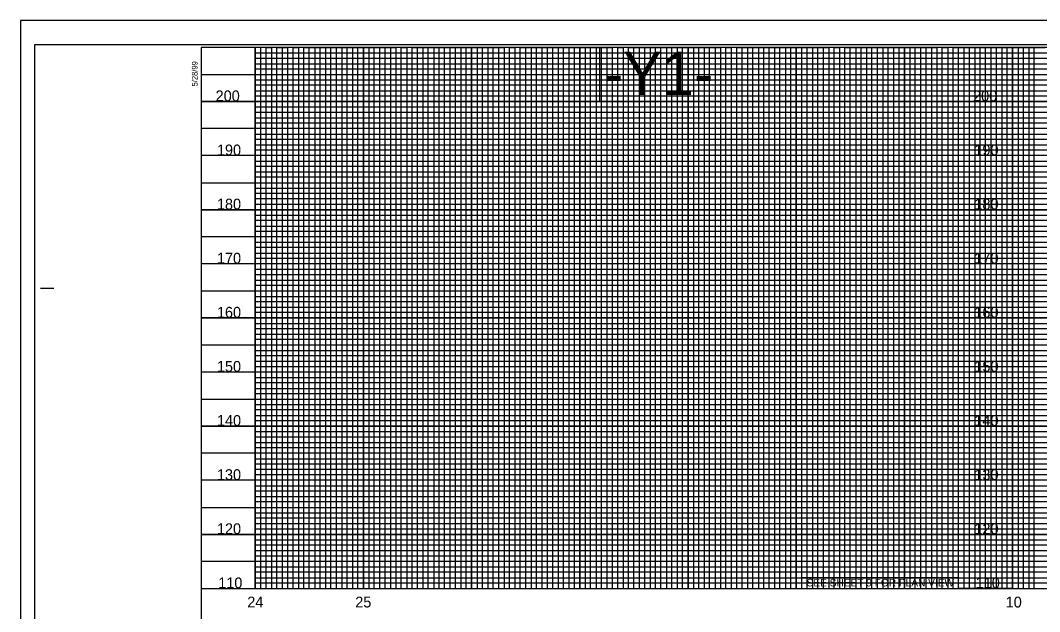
# Model space of a CAD drawing. Extents: x 1779926 to 1781626, y 618464 to 619564.
# Drawn here: x 1779926 to 1780868, y 619018 to 619564 of the extents above; entities that cross this region are included whole.
import ezdxf

# ---------------------------------------------------------------- set-up
doc = ezdxf.new("R2010")
doc.units = 0
for name, color, linetype in [('Exist Vertical Profile Horizontal Axis Label Major', 7, 'Continuous'), ('Exist Vertical Profile Vertical Axis Label', 7, 'Continuous'), ('Prop DSN Text', 7, 'Continuous'), ('Prop Grid Mask', 7, 'Continuous'), ('Sheet DOT Grid CELL', 7, 'Continuous'), ('Sheet Layout Profile Border Port 1', 7, 'Continuous'), ('Sheet Plot Border Inside CELL', 7, 'Continuous'), ('Sheet Plot Border Outside CELL', 7, 'Continuous'), ('Sheet Profile CELL', 7, 'Continuous'), ('Sheet Profile Grid Major CELL', 7, 'Continuous'), ('Sheet Profile Grid Middle CELL', 7, 'Continuous'), ('Sheet Profile Grid Minor CELL', 7, 'Continuous')]:
    doc.layers.add(name, color=color, linetype=linetype)

msp = doc.modelspace()

# ---------------------------------------------------------------- linework, layer by layer
at = {"layer": 'Prop Grid Mask'}
for points in [[(1780577.96, 619539.19), (1780461.31, 619539.19), (1780461.31, 619489.19), (1780577.96, 619489.19)], [(1780792.96, 619539.19), (1780842.96, 619539.19), (1780842.96, 619039.19), (1780792.96, 619039.19)], [(1780792.96, 619049.19), (1780647.96, 619049.19), (1780647.96, 619039.19), (1780792.96, 619039.19)]]:
    msp.add_lwpolyline(points, close=True, dxfattribs=at)
at = {"layer": 'Sheet DOT Grid CELL'}
for p, q in [((1780142.96, 619039.19), (1780142.96, 619539.19)), ((1780192.96, 619039.19), (1780192.96, 619539.19)), ((1780242.96, 619039.19), (1780242.96, 619539.19)), ((1780292.96, 619039.19), (1780292.96, 619539.19)), ((1780342.96, 619039.19), (1780342.96, 619539.19)), ((1780392.96, 619039.19), (1780392.96, 619539.19)), ((1780392.96, 619039.19), (1780392.96, 619539.19)), ((1780442.96, 619039.19), (1780442.96, 619539.19)), ((1780492.96, 619039.19), (1780492.96, 619539.19)), ((1780542.96, 619039.19), (1780542.96, 619539.19)), ((1780592.96, 619039.19), (1780592.96, 619539.19)), ((1780642.96, 619039.19), (1780642.96, 619539.19)), ((1780692.96, 619039.19), (1780692.96, 619539.19)), ((1780742.96, 619039.19), (1780742.96, 619539.19)), ((1780792.96, 619039.19), (1780792.96, 619539.19)), ((1780842.96, 619039.19), (1780842.96, 619539.19)), ((1781392.91, 619489.19), (1780092.96, 619489.19)), ((1781392.91, 619439.19), (1780092.96, 619439.19)), ((1781392.96, 619389.19), (1780092.96, 619389.19)), ((1781392.91, 619339.19), (1780092.96, 619339.19)), ((1781592.96, 619289.19), (1780092.96, 619289.19)), ((1781592.96, 619239.19), (1780092.96, 619239.19)), ((1781592.96, 619189.19), (1780092.96, 619189.19)), ((1781592.96, 619139.19), (1780092.96, 619139.19)), ((1781592.96, 619089.19), (1780092.96, 619089.19))]:
    msp.add_line(p, q, dxfattribs=at)
at = {"layer": 'Sheet Layout Profile Border Port 1'}
for points in [[(1781542.96, 619099.19), (1781542.96, 619314.19), (1781392.91, 619314.19), (1781392.96, 619539.19), (1780142.96, 619539.19), (1780142.96, 619039.19), (1781542.96, 619039.19), (1781542.96, 619049.19)], [(1780142.96, 619378.14), (1780142.96, 619039.19), (1781542.96, 619039.19), (1781542.96, 619314.19)]]:
    msp.add_lwpolyline(points, dxfattribs=at)
at = {"layer": 'Sheet Plot Border Inside CELL'}
msp.add_lwpolyline([(1779938.96, 618486.64), (1781605.46, 618486.64), (1781605.46, 619541.74), (1779938.96, 619541.74)], close=True, dxfattribs=at)
at = {"layer": 'Sheet Plot Border Outside CELL'}
msp.add_lwpolyline([(1779925.96, 618464.19), (1781625.96, 618464.19), (1781625.96, 619564.19), (1779925.96, 619564.19)], close=True, dxfattribs=at)
at = {"layer": 'Sheet Profile CELL'}
for p, q in [((1779944.46, 619316.69), (1779956.96, 619316.69)), ((1780092.96, 619039.19), (1781592.96, 619039.19))]:
    msp.add_line(p, q, dxfattribs=at)
msp.add_lwpolyline([(1781592.96, 619539.19), (1780092.96, 619539.19), (1780092.96, 618489.19), (1781592.96, 618489.19)], close=True, dxfattribs=at)
at = {"layer": 'Sheet Profile Grid Major CELL'}
for points in [[(1780142.96, 619539.19), (1780142.96, 619039.19), (1780192.96, 619039.19), (1780192.96, 619539.19), (1780242.96, 619539.19), (1780242.96, 619039.19), (1780292.96, 619039.19), (1780292.96, 619539.19), (1780342.96, 619539.19), (1780342.96, 619039.19), (1780392.96, 619039.19), (1780392.96, 619539.19), (1780442.96, 619539.19), (1780442.96, 619039.19), (1780492.96, 619039.19), (1780492.96, 619539.19), (1780542.96, 619539.19), (1780542.96, 619039.19), (1780592.96, 619039.19), (1780592.96, 619539.19), (1780642.96, 619539.19), (1780642.96, 619039.19), (1780692.96, 619039.19), (1780692.96, 619539.19), (1780742.96, 619539.19), (1780742.96, 619039.19), (1780792.96, 619039.19), (1780792.96, 619539.19), (1780842.96, 619539.19), (1780842.96, 619039.19), (1780892.96, 619039.19)], [(1780092.96, 619489.19), (1781392.96, 619489.19)], [(1781392.96, 619439.19), (1780092.96, 619439.19), (1780092.96, 619389.19), (1781392.96, 619389.19)], [(1781392.96, 619339.19), (1780092.96, 619339.19), (1780092.96, 619289.19), (1781592.96, 619289.19)], [(1781592.96, 619239.19), (1780092.96, 619239.19), (1780092.96, 619189.19), (1781592.96, 619189.19)], [(1781592.96, 619139.19), (1780092.96, 619139.19), (1780092.96, 619139.19), (1780092.96, 619089.19), (1781592.96, 619089.19)]]:
    msp.add_lwpolyline(points, dxfattribs=at)
at = {"layer": 'Sheet Profile Grid Middle CELL'}
msp.add_line((1780092.96, 619514.19), (1781392.91, 619514.19), dxfattribs=at)
for points in [[(1780167.96, 619539.19), (1780167.96, 619039.19), (1780217.96, 619039.19), (1780217.96, 619539.19), (1780267.96, 619539.19), (1780267.96, 619039.19), (1780317.96, 619039.19), (1780317.96, 619539.19), (1780367.96, 619539.19), (1780367.96, 619039.19), (1780417.96, 619039.19), (1780417.96, 619539.19), (1780467.96, 619539.19), (1780467.96, 619039.19), (1780517.96, 619039.19), (1780517.96, 619539.19), (1780567.96, 619539.19), (1780567.96, 619039.19), (1780617.96, 619039.19), (1780617.96, 619539.19), (1780667.96, 619539.19), (1780667.96, 619039.19), (1780717.96, 619039.19), (1780717.96, 619039.19), (1780717.96, 619539.19), (1780767.96, 619539.19), (1780767.96, 619039.19), (1780817.96, 619039.19), (1780817.96, 619539.19), (1780867.96, 619539.19)], [(1781392.96, 619464.19), (1780092.96, 619464.19), (1780092.96, 619414.19), (1781392.96, 619414.19)], [(1781392.91, 619364.19), (1780092.96, 619364.19), (1780092.96, 619314.19), (1781417.96, 619314.19)], [(1781592.96, 619264.19), (1780092.96, 619264.19), (1780092.96, 619214.19), (1781592.96, 619214.19)], [(1781592.96, 619164.19), (1780092.96, 619164.19), (1780092.96, 619114.19), (1781592.96, 619114.19)], [(1781592.96, 619064.19), (1780092.96, 619064.19)]]:
    msp.add_lwpolyline(points, dxfattribs=at)
at = {"layer": 'Sheet Profile Grid Minor CELL'}
for p, q in [((1780142.96, 619534.19), (1781392.96, 619534.19)), ((1780142.96, 619529.19), (1780142.96, 619529.19)), ((1781392.96, 619529.19), (1780142.96, 619528.84)), ((1780142.96, 619524.19), (1781392.96, 619524.19)), ((1781392.91, 619404.19), (1780142.96, 619404.19)), ((1781392.96, 619399.19), (1780142.96, 619399.19)), ((1781392.96, 619394.19), (1780142.96, 619394.19)), ((1780142.96, 619384.19), (1781392.96, 619384.19)), ((1781392.96, 619379.19), (1780142.96, 619379.19)), ((1780142.96, 619374.19), (1781392.91, 619374.19)), ((1781392.91, 619354.19), (1780142.96, 619354.19)), ((1780142.96, 619349.19), (1781392.91, 619349.19)), ((1781392.91, 619329.19), (1780142.96, 619329.19)), ((1780142.96, 619324.19), (1781392.91, 619324.19)), ((1781542.96, 619304.19), (1780142.96, 619304.19)), ((1780142.96, 619299.19), (1781542.96, 619299.19)), ((1781542.96, 619294.19), (1780142.96, 619294.19)), ((1780142.96, 619284.19), (1781542.96, 619284.19)), ((1781542.96, 619279.19), (1780142.96, 619279.19)), ((1780142.96, 619274.19), (1781542.96, 619274.19)), ((1781542.96, 619269.19), (1780142.96, 619269.19)), ((1780142.96, 619259.19), (1781542.96, 619259.19)), ((1781542.96, 619254.19), (1780142.96, 619254.19)), ((1780142.96, 619249.19), (1781542.96, 619249.19)), ((1781542.96, 619244.19), (1780142.96, 619244.19)), ((1780142.96, 619234.19), (1781542.96, 619234.19)), ((1781542.96, 619229.19), (1780142.96, 619229.19)), ((1780142.96, 619224.19), (1781542.96, 619224.19)), ((1781542.96, 619219.19), (1780142.96, 619219.19)), ((1780142.96, 619209.19), (1781542.96, 619209.19)), ((1781542.96, 619204.19), (1780142.96, 619204.19)), ((1780142.96, 619199.19), (1781542.96, 619199.19)), ((1781542.96, 619194.19), (1780142.96, 619194.19)), ((1780142.96, 619184.19), (1781542.96, 619184.19)), ((1781542.96, 619179.19), (1780142.96, 619179.19)), ((1780142.96, 619174.19), (1781542.96, 619174.19)), ((1781542.96, 619169.19), (1780142.96, 619169.19)), ((1780142.96, 619159.19), (1781542.96, 619159.19)), ((1781542.96, 619154.19), (1780142.96, 619154.19)), ((1781542.96, 619149.19), (1780142.96, 619149.19)), ((1781542.96, 619144.19), (1780142.96, 619144.19)), ((1780142.96, 619134.19), (1781542.96, 619134.19)), ((1781542.96, 619129.19), (1780142.96, 619129.19)), ((1780142.96, 619124.19), (1781542.96, 619124.19)), ((1781542.96, 619119.19), (1780142.96, 619119.19)), ((1780142.96, 619109.19), (1781542.96, 619109.19)), ((1781542.96, 619104.19), (1780142.96, 619104.19)), ((1780142.96, 619099.19), (1781542.96, 619099.19)), ((1781542.96, 619094.19), (1780142.96, 619094.19)), ((1780142.96, 619084.19), (1781542.96, 619084.19)), ((1781542.96, 619079.19), (1780142.96, 619079.19)), ((1780142.96, 619074.19), (1781542.96, 619074.19)), ((1781542.96, 619069.19), (1780142.96, 619069.19)), ((1780142.96, 619059.19), (1781542.96, 619059.19)), ((1781542.96, 619054.19), (1780142.96, 619054.19)), ((1780142.96, 619049.19), (1781542.96, 619049.19))]:
    msp.add_line(p, q, dxfattribs=at)
for points in [[(1780147.96, 619539.19), (1780147.96, 619039.19), (1780152.96, 619039.19), (1780152.96, 619539.19), (1780157.96, 619539.19), (1780157.96, 619039.19), (1780162.96, 619039.19), (1780162.96, 619539.19), (1780172.96, 619539.19), (1780172.96, 619039.19), (1780177.96, 619039.19), (1780177.96, 619539.19), (1780182.96, 619539.19), (1780182.96, 619039.19), (1780187.96, 619039.19), (1780197.96, 619039.19), (1780202.96, 619039.19), (1780202.96, 619539.19), (1780207.96, 619539.19), (1780207.96, 619039.19), (1780212.96, 619039.19), (1780212.96, 619539.19), (1780222.96, 619539.19), (1780222.96, 619039.19), (1780227.96, 619039.19), (1780227.96, 619539.19), (1780232.96, 619539.19), (1780232.96, 619039.19), (1780237.96, 619039.19), (1780237.96, 619539.19), (1780247.96, 619539.19), (1780247.96, 619039.19), (1780252.96, 619039.19), (1780252.96, 619539.19), (1780257.96, 619539.19), (1780257.96, 619039.19), (1780262.96, 619039.19), (1780262.96, 619539.19), (1780272.96, 619539.19), (1780272.96, 619039.19), (1780277.96, 619039.19), (1780277.96, 619539.19), (1780282.96, 619539.19), (1780282.96, 619039.19), (1780287.96, 619039.19), (1780287.96, 619539.19), (1780297.96, 619539.19), (1780297.96, 619039.19), (1780302.96, 619039.19), (1780302.96, 619539.19), (1780307.96, 619539.19), (1780307.96, 619039.19), (1780312.96, 619039.19), (1780312.96, 619539.19), (1780322.96, 619539.19), (1780322.96, 619039.19), (1780327.96, 619039.19), (1780327.96, 619539.19), (1780332.96, 619539.19), (1780332.96, 619039.19), (1780337.96, 619039.19), (1780337.96, 619539.19), (1780347.96, 619539.19), (1780347.96, 619039.19), (1780352.96, 619039.19), (1780352.96, 619539.19), (1780357.96, 619539.19), (1780357.96, 619039.19)], [(1780187.96, 619039.19), (1780187.96, 619539.19), (1780197.96, 619539.19), (1780197.96, 619039.19)], [(1780357.96, 619039.19), (1780362.96, 619039.19), (1780362.96, 619539.19), (1780372.96, 619539.19), (1780372.96, 619039.19), (1780377.96, 619039.19), (1780377.96, 619539.19), (1780382.96, 619539.19), (1780382.96, 619039.19), (1780387.96, 619039.19), (1780387.96, 619539.19), (1780397.96, 619539.19), (1780397.96, 619039.19), (1780402.96, 619039.19), (1780402.96, 619539.19), (1780407.96, 619539.19), (1780407.96, 619039.19), (1780412.96, 619039.19), (1780412.96, 619539.19), (1780422.96, 619539.19), (1780422.96, 619039.19), (1780427.96, 619039.19), (1780427.96, 619539.19), (1780432.96, 619539.19), (1780432.96, 619039.19), (1780437.96, 619039.19), (1780437.96, 619539.19), (1780447.96, 619539.19), (1780447.96, 619039.19), (1780452.96, 619039.19), (1780452.96, 619539.19), (1780457.96, 619539.19), (1780457.96, 619039.19), (1780462.96, 619039.19), (1780462.96, 619539.19), (1780472.96, 619539.19), (1780472.96, 619039.19), (1780477.96, 619039.19), (1780477.96, 619539.19), (1780482.96, 619539.19), (1780482.96, 619039.19), (1780487.96, 619039.19), (1780487.96, 619539.19), (1780497.96, 619539.19), (1780497.96, 619039.19), (1780502.96, 619039.19), (1780502.96, 619539.19), (1780507.96, 619539.19), (1780507.96, 619039.19), (1780512.96, 619039.19), (1780512.96, 619539.19), (1780522.96, 619539.19), (1780522.96, 619039.19), (1780527.96, 619039.19), (1780527.96, 619539.19), (1780532.96, 619539.19), (1780532.96, 619039.19), (1780537.96, 619039.19), (1780537.96, 619539.19), (1780547.96, 619539.19), (1780547.96, 619039.19), (1780552.96, 619039.19), (1780552.96, 619539.19), (1780557.96, 619539.19), (1780557.96, 619039.19), (1780562.96, 619039.19), (1780562.96, 619539.19), (1780572.96, 619539.19), (1780572.96, 619039.19), (1780577.96, 619039.19), (1780577.96, 619539.19), (1780582.96, 619539.19), (1780582.96, 619039.19), (1780587.96, 619039.19), (1780587.96, 619539.19), (1780597.96, 619539.19), (1780597.96, 619039.19), (1780602.96, 619039.19), (1780602.96, 619539.19), (1780607.96, 619539.19), (1780607.96, 619039.19), (1780612.96, 619039.19), (1780612.96, 619539.19), (1780622.96, 619539.19), (1780622.96, 619039.19), (1780627.96, 619039.19), (1780627.96, 619539.19), (1780632.96, 619539.19), (1780632.96, 619039.19), (1780637.96, 619039.19), (1780637.96, 619539.19), (1780647.96, 619539.19), (1780647.96, 619039.19), (1780652.96, 619039.19), (1780652.96, 619539.19), (1780657.96, 619539.19), (1780657.96, 619039.19), (1780662.96, 619039.19), (1780662.96, 619539.19), (1780672.96, 619539.19)], [(1780672.96, 619539.19), (1780672.96, 619039.19), (1780677.96, 619039.19), (1780677.96, 619539.19), (1780682.96, 619539.19), (1780682.96, 619039.19), (1780687.96, 619039.19), (1780687.96, 619539.19), (1780697.96, 619539.19), (1780697.96, 619039.19), (1780702.96, 619039.19), (1780702.96, 619539.19), (1780707.96, 619539.19), (1780707.96, 619039.19), (1780712.96, 619039.19), (1780712.96, 619539.19), (1780722.96, 619539.19), (1780722.96, 619039.19), (1780727.96, 619039.19), (1780727.96, 619539.19), (1780732.96, 619539.19), (1780732.96, 619039.19), (1780737.96, 619039.19), (1780737.96, 619539.19), (1780747.96, 619539.19), (1780747.96, 619039.19), (1780752.96, 619039.19), (1780752.96, 619539.19), (1780757.96, 619539.19), (1780757.96, 619039.19), (1780762.96, 619039.19), (1780762.96, 619539.19), (1780772.96, 619539.19), (1780772.96, 619039.19), (1780777.96, 619039.19), (1780777.96, 619539.19), (1780782.96, 619539.19), (1780782.96, 619039.19), (1780787.96, 619039.19), (1780787.96, 619539.19), (1780797.96, 619539.19), (1780797.96, 619039.19), (1780797.96, 619039.19), (1780802.96, 619039.19), (1780802.96, 619539.19), (1780807.96, 619539.19), (1780807.96, 619039.19), (1780812.96, 619039.19), (1780812.96, 619539.19), (1780822.96, 619539.19), (1780822.96, 619039.19), (1780827.96, 619039.19), (1780827.96, 619539.19), (1780832.96, 619539.19), (1780832.96, 619039.19), (1780837.96, 619039.19), (1780837.96, 619539.19), (1780847.96, 619539.19), (1780847.96, 619039.19), (1780852.96, 619039.19), (1780852.96, 619539.19), (1780857.96, 619539.19), (1780857.96, 619039.19), (1780862.96, 619039.19), (1780862.96, 619539.19), (1780872.96, 619539.19)], [(1781392.96, 619519.19), (1780142.96, 619519.19), (1780142.96, 619509.19), (1781392.96, 619509.19)], [(1781392.91, 619504.19), (1780142.96, 619504.19), (1780142.96, 619499.19), (1781392.96, 619499.19)], [(1781392.96, 619494.19), (1780142.96, 619494.19), (1780142.96, 619484.19), (1781392.96, 619484.19)], [(1781392.96, 619479.19), (1780142.96, 619479.19), (1780142.96, 619474.19), (1781392.96, 619474.19)], [(1781392.96, 619469.19), (1780142.96, 619469.19), (1780142.96, 619459.19), (1781392.96, 619459.19)], [(1781392.96, 619454.19), (1780142.96, 619454.19), (1780142.96, 619449.19), (1781392.96, 619449.19)], [(1781392.96, 619444.19), (1780142.96, 619444.19), (1780142.96, 619434.19), (1781392.96, 619434.19)], [(1781392.96, 619429.09), (1780143.06, 619429.09), (1780143.06, 619424.19), (1781392.96, 619424.19)], [(1781392.96, 619419.19), (1780142.96, 619419.19), (1780142.96, 619409.19), (1781392.96, 619409.19)], [(1781392.91, 619369.19), (1780142.96, 619369.19), (1780142.96, 619359.19), (1781392.91, 619359.19)], [(1781392.91, 619344.19), (1780142.96, 619344.19), (1780142.96, 619334.19), (1781392.91, 619334.19)], [(1781392.91, 619319.19), (1780142.96, 619319.19), (1780142.96, 619309.19), (1781542.96, 619309.19)], [(1781542.96, 619044.19), (1780142.96, 619044.19)]]:
    msp.add_lwpolyline(points, dxfattribs=at)

# ---------------------------------------------------------------- texts
at = {"layer": 'Exist Vertical Profile Horizontal Axis Label Major'}
for s, p in [('24', (1780135.62, 619021.69)), ('25', (1780235.41, 619021.69)), ('10', (1780836.54, 619021.69))]:
    msp.add_text(s, height=10, dxfattribs=at).set_placement(p)
at = {"layer": 'Exist Vertical Profile Vertical Axis Label'}
for s, p in [('200', (1780106.39, 619489.44)), ('200', (1780806.39, 619489.44)), ('190', (1780107.59, 619439.44)), ('190', (1780807.59, 619439.44)), ('180', (1780107.59, 619389.44)), ('180', (1780807.59, 619389.44)), ('170', (1780107.59, 619339.44)), ('170', (1780807.59, 619339.44)), ('160', (1780107.59, 619289.44)), ('160', (1780807.59, 619289.44)), ('150', (1780107.59, 619239.44)), ('150', (1780807.59, 619239.44)), ('140', (1780107.59, 619189.44)), ('140', (1780807.59, 619189.44)), ('130', (1780107.59, 619139.44)), ('130', (1780807.59, 619139.44)), ('120', (1780107.59, 619089.44)), ('120', (1780807.59, 619089.44)), ('110', (1780108.79, 619039.44)), ('110', (1780808.79, 619039.44))]:
    msp.add_text(s, height=10, dxfattribs=at).set_placement(p)
at = {"layer": 'Prop DSN Text'}
for s, height, p in [('-Y1-', 40, (1780465.23, 619495.14)), ('SEE SHEET 9 FOR PLAN VIEW', 7, (1780652.54, 619041.14))]:
    msp.add_text(s, height=height, dxfattribs=at).set_placement(p)
at = {"layer": 'Sheet Profile CELL'}
msp.add_text('5/28/99', height=5.25, rotation=90, dxfattribs=at).set_placement((1780089.72, 619503.1))

doc.saveas('drawing.dxf')
